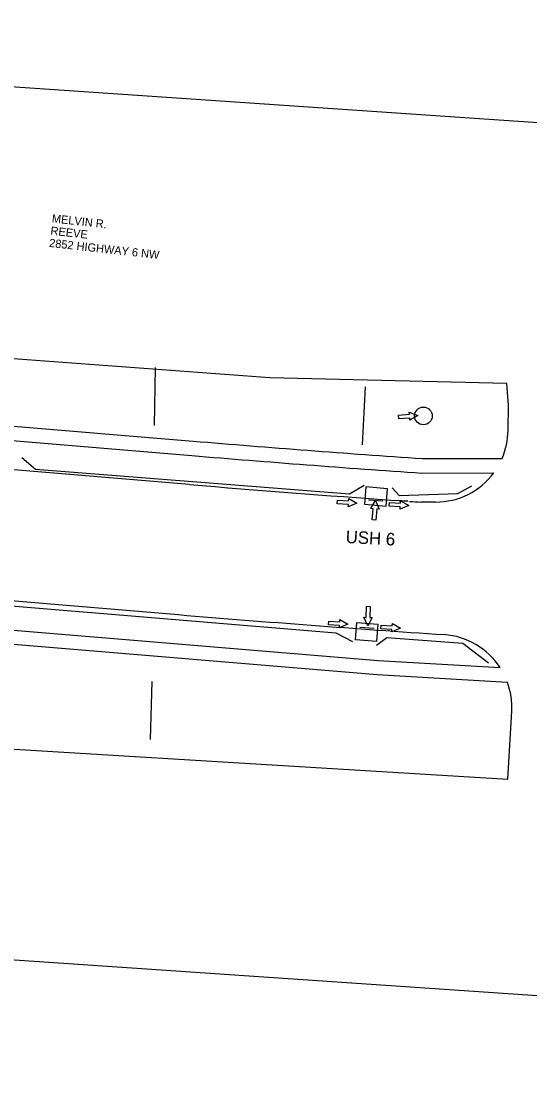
# Model space of a CAD drawing. Extents: x 20499990 to 20505779, y 7953198 to 7954399.
# Drawn here: x 20504373.6 to 20504548.7, y 7953486.1 to 7953849.5 of the extents above; entities that cross this region are included whole.
import ezdxf

# ---------------------------------------------------------------- set-up
doc = ezdxf.new("R2010")
doc.units = 0
for name, color, linetype in [('Building', 7, 'Continuous'), ('dsnCellElements', 7, 'Continuous'), ('ErosionControl', 7, 'Continuous'), ('NamedBoundary', 7, 'Continuous'), ('Seeding', 7, 'Continuous'), ('Text', 7, 'Continuous')]:
    doc.layers.add(name, color=color, linetype=linetype)

msp = doc.modelspace()

# ---------------------------------------------------------------- linework, layer by layer
at = {"layer": 'Building'}
for p, q in [((20504541.25, 7953717.22), (20504540.74, 7953724.7)), ((20504541.13, 7953708.44), (20504541.25, 7953717.22)), ((20504368.14, 7953710.18), (20504432.72, 7953704.8)), ((20504367.73, 7953705.2), (20504432.3, 7953699.81)), ((20504511.66, 7953698.76), (20504539.08, 7953698.85)), ((20504431.47, 7953689.85), (20504366.9, 7953695.23)), ((20504511.5, 7953693.76), (20504536.19, 7953693.84)), ((20504266.74, 7953648.4), (20504496.4, 7953629.24)), ((20504496.05, 7953624.25), (20504265.83, 7953643.46)), ((20504496.4, 7953629.24), (20504538.38, 7953626.82)), ((20504540.95, 7953621.66), (20504496.05, 7953624.25)), ((20504541.05, 7953588.36), (20504542.39, 7953611.73))]:
    msp.add_line(p, q, dxfattribs=at)
for points in [[(20504540.74, 7953724.7), (20504459.18, 7953726.62), (20504297.96, 7953738.54), (20504285.39, 7953744.8), (20504230.72, 7953759.28), (20504230.66, 7953757.1), (20504230.6, 7953755.01), (20504230.5, 7953751.64)], [(20504427.73, 7953645), (20504246.09, 7953660.16), (20503289.64, 7953739.98)], [(20504506.56, 7953684.05), (20504506.56, 7953684.01), (20504502.25, 7953684.32), (20504502.26, 7953684.38)], [(20504219.46, 7953604.68), (20504299.4, 7953598.01), (20504299.45, 7953603.02), (20504541.05, 7953588.36)]]:
    msp.add_lwpolyline(points, dxfattribs=at)
for centre, radius, start, end in [((20504516.14, 7953708.78), 25, 336.6115, 359.2393), ((20504906, 7959377.59), 5692.5, 265.23083, 266.02776), ((20504906, 7959377.59), 5697.5, 265.23083, 266.02959), ((20504516.14, 7953708.78), 25, 270.1897, 323.3198), ((20504906, 7959377.59), 5707.5, 265.23083, 265.94355), ((20504906, 7959377.59), 5752.5, 265.230833, 266.143653), ((20504517.43, 7953613.17), 25, 33.0939, 86.1437), ((20504517.43, 7953613.17), 25, 356.7119, 19.8623)]:
    msp.add_arc(centre, radius, start, end, dxfattribs=at)
at = {"layer": 'dsnCellElements'}
for p, q in [((20504503.4, 7953713.74), (20504507.2, 7953714.04)), ((20504503.5, 7953712.47), (20504503.4, 7953713.74)), ((20504507.3, 7953712.77), (20504503.5, 7953712.47)), ((20504507.14, 7953714.83), (20504510.11, 7953713.62)), ((20504507.2, 7953714.04), (20504507.14, 7953714.83)), ((20504507.36, 7953711.97), (20504507.3, 7953712.77)), ((20504510.11, 7953713.62), (20504507.36, 7953711.97)), ((20504482.37, 7953683.17), (20504482.44, 7953684.44)), ((20504486.18, 7953682.95), (20504482.37, 7953683.17)), ((20504482.44, 7953684.44), (20504486.25, 7953684.22)), ((20504489.08, 7953683.43), (20504486.14, 7953682.16)), ((20504486.14, 7953682.16), (20504486.18, 7953682.95)), ((20504486.25, 7953684.22), (20504486.3, 7953685.02)), ((20504486.3, 7953685.02), (20504489.08, 7953683.43)), ((20504493.89, 7953681.58), (20504495.53, 7953684.33)), ((20504495.53, 7953684.33), (20504496.74, 7953681.37)), ((20504500.25, 7953682.36), (20504500.32, 7953683.63)), ((20504504.06, 7953682.14), (20504500.25, 7953682.36)), ((20504500.32, 7953683.63), (20504504.13, 7953683.41)), ((20504506.95, 7953682.61), (20504504.01, 7953681.34)), ((20504504.13, 7953683.41), (20504504.18, 7953684.2)), ((20504504.18, 7953684.2), (20504506.95, 7953682.61)), ((20504494.68, 7953681.52), (20504493.89, 7953681.58)), ((20504494.39, 7953677.72), (20504494.68, 7953681.52)), ((20504495.95, 7953681.43), (20504495.66, 7953677.62)), ((20504496.74, 7953681.37), (20504495.95, 7953681.43)), ((20504504.01, 7953681.34), (20504504.06, 7953682.14)), ((20504495.66, 7953677.62), (20504494.39, 7953677.72)), ((20504492.33, 7953644.07), (20504492.47, 7953647.89)), ((20504492.47, 7953647.89), (20504493.74, 7953647.84)), ((20504493.74, 7953647.84), (20504493.6, 7953644.03)), ((20504479.32, 7953641.53), (20504479.41, 7953642.8)), ((20504479.41, 7953642.8), (20504483.22, 7953642.54)), ((20504483.22, 7953642.54), (20504483.27, 7953643.33)), ((20504483.27, 7953643.33), (20504486.03, 7953641.71)), ((20504492.85, 7953641.19), (20504491.53, 7953644.1)), ((20504491.53, 7953644.1), (20504492.33, 7953644.07)), ((20504494.39, 7953644), (20504492.85, 7953641.19)), ((20504493.6, 7953644.03), (20504494.39, 7953644)), ((20504483.13, 7953641.27), (20504479.32, 7953641.53)), ((20504486.03, 7953641.71), (20504483.07, 7953640.48)), ((20504483.07, 7953640.48), (20504483.13, 7953641.27)), ((20504497.38, 7953640.17), (20504497.46, 7953641.44)), ((20504501.19, 7953639.93), (20504497.38, 7953640.17)), ((20504497.46, 7953641.44), (20504501.27, 7953641.2)), ((20504504.09, 7953640.39), (20504501.14, 7953639.14)), ((20504501.14, 7953639.14), (20504501.19, 7953639.93)), ((20504501.27, 7953641.2), (20504501.32, 7953642)), ((20504501.32, 7953642), (20504504.09, 7953640.39))]:
    msp.add_line(p, q, dxfattribs=at)
at = {"layer": 'ErosionControl'}
for p, q in [((20504419.45, 7953710.14), (20504419.84, 7953730.14)), ((20504491.1, 7953703.58), (20504492.1, 7953723.56)), ((20504498.1, 7953684.14), (20504493.11, 7953684.49)), ((20504516.22, 7953683.78), (20504511.17, 7953683.76)), ((20504490.09, 7953640.69), (20504495.07, 7953640.3)), ((20504418.57, 7953621.99), (20504417.92, 7953602))]:
    msp.add_line(p, q, dxfattribs=at)
for points in [[(20504373.78, 7953699.21), (20504378.48, 7953695.09), (20504486.57, 7953686.61), (20504491.61, 7953689.59)], [(20504501.23, 7953688.67), (20504503.64, 7953686.04), (20504523.9, 7953686.73), (20504528.71, 7953689.36)], [(20504364.18, 7953645.5), (20504367.41, 7953648.26), (20504481.84, 7953638.74), (20504487.64, 7953635.79)], [(20504495.82, 7953634.55), (20504499.43, 7953637.12), (20504525.59, 7953635.13), (20504534.43, 7953628.37)]]:
    msp.add_lwpolyline(points, dxfattribs=at)
for points in [[(20504492.15, 7953689.01), (20504491.68, 7953683.03), (20504499.23, 7953682.43), (20504499.7, 7953688.41)], [(20504489.07, 7953642.27), (20504496.29, 7953641.7), (20504495.83, 7953635.81), (20504488.6, 7953636.38)]]:
    msp.add_lwpolyline(points, close=True, dxfattribs=at)
msp.add_circle((20504512.01, 7953713.48), 3.04, dxfattribs=at)
msp.add_arc((20504906, 7959377.59), 5707.5, 265.99374, 266.03323, dxfattribs=at)
at = {"layer": 'NamedBoundary'}
msp.add_lwpolyline([(20504038.63, 7953849.54), (20504018.15, 7953550.24), (20504956.36, 7953486.07), (20504976.83, 7953785.37)], close=True, dxfattribs=at)
at = {"layer": 'Seeding'}
for p, q in [((20504541.25, 7953717.22), (20504540.74, 7953724.7)), ((20504541.13, 7953708.44), (20504541.25, 7953717.22)), ((20504368.14, 7953710.18), (20504432.72, 7953704.8)), ((20504367.73, 7953705.2), (20504432.3, 7953699.81)), ((20504511.66, 7953698.76), (20504539.08, 7953698.85)), ((20504431.47, 7953689.85), (20504366.9, 7953695.23)), ((20504511.5, 7953693.76), (20504536.19, 7953693.84)), ((20504516.22, 7953683.78), (20504511.17, 7953683.76)), ((20504266.74, 7953648.4), (20504496.4, 7953629.24)), ((20504496.05, 7953624.25), (20504265.83, 7953643.46)), ((20504496.4, 7953629.24), (20504538.38, 7953626.82)), ((20504540.95, 7953621.66), (20504496.05, 7953624.25)), ((20504541.05, 7953588.36), (20504542.39, 7953611.73))]:
    msp.add_line(p, q, dxfattribs=at)
for points in [[(20504540.74, 7953724.7), (20504459.18, 7953726.62), (20504297.96, 7953738.54), (20504285.39, 7953744.8), (20504230.72, 7953759.28), (20504230.99, 7953784.34), (20504204.68, 7953786.54), (20504205.13, 7953776.82)], [(20504427.73, 7953645), (20504246.09, 7953660.16), (20503289.64, 7953739.98)], [(20504506.61, 7953684.05), (20504506.62, 7953684.07), (20504502.26, 7953684.38), (20504502.26, 7953684.38)], [(20504209.76, 7953585.42), (20504219.25, 7953584.63), (20504219.46, 7953604.68), (20504299.4, 7953598.01), (20504299.45, 7953603.02), (20504541.05, 7953588.36)]]:
    msp.add_lwpolyline(points, dxfattribs=at)
for centre, radius, start, end in [((20504516.14, 7953708.78), 25, 336.6115, 359.2393), ((20504906, 7959377.59), 5692.5, 265.23083, 266.02776), ((20504906, 7959377.59), 5697.5, 265.23083, 266.02959), ((20504516.14, 7953708.78), 25, 270.1897, 323.3198), ((20504906, 7959377.59), 5707.5, 265.23083, 265.94355), ((20504906, 7959377.59), 5707.5, 265.99374, 266.03323), ((20504906, 7959377.59), 5752.5, 265.230833, 266.143653), ((20504517.43, 7953613.17), 25, 33.0939, 86.1437), ((20504517.43, 7953613.17), 25, 356.7119, 19.8623)]:
    msp.add_arc(centre, radius, start, end, dxfattribs=at)

# ---------------------------------------------------------------- texts
at = {"layer": 'Text'}
for s, height, rotation, p in [('MELVIN R. ', 2.835, 353.6591, (20504384.02, 7953780.2)), ('REEVE', 2.835, 353.6591, (20504383.55, 7953775.97)), ('2852 HIGHWAY 6 NW', 2.8346, 353.6591, (20504383.08, 7953771.75)), ('USH 6', 4.32, 356.9, (20504485.18, 7953669.71))]:
    msp.add_text(s, height=height, rotation=rotation, dxfattribs=at).set_placement(p)

doc.saveas('drawing.dxf')
